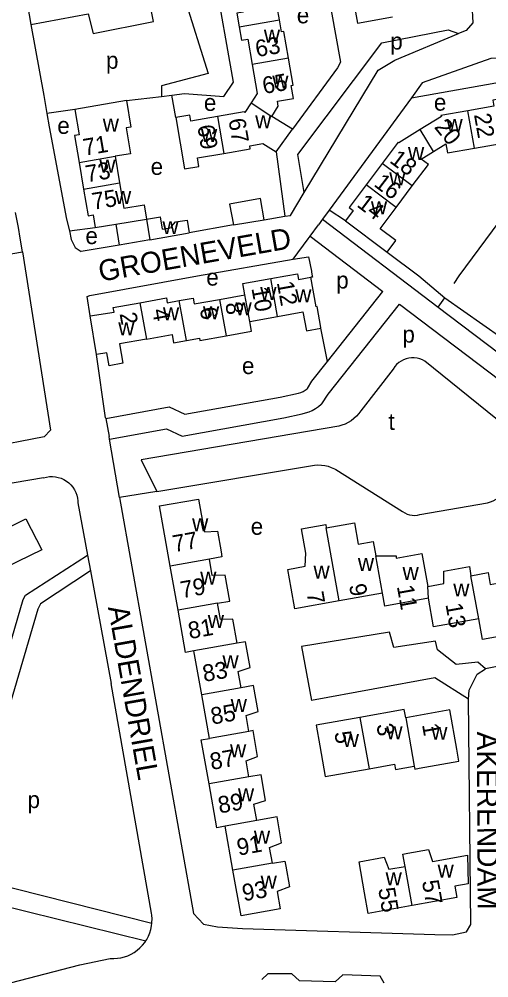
# Model space of a CAD drawing. Extents: x 157794 to 159375, y 380877 to 382306.
# Drawn here: x 158787.7 to 158899.5, y 381333.1 to 381561.1 of the extents above; entities that cross this region are included whole.
import ezdxf

# ---------------------------------------------------------------- set-up
doc = ezdxf.new("R2010")
doc.units = 0
for name, color, linetype in [('BLT_Basislijn', 7, 'Continuous'), ('BLT_Bebouwing', 7, 'Continuous'), ('BLT_Centroide', 7, 'Continuous'), ('BLT_Huisnummer', 7, 'Continuous'), ('BLT_Huisnummer_ tussenligend', 7, 'Continuous'), ('BLT_Onderverdeling_panden', 7, 'Continuous'), ('BLT_Straatnaam', 7, 'Continuous')]:
    doc.layers.add(name, color=color, linetype=linetype)

msp = doc.modelspace()

# ---------------------------------------------------------------- linework, layer by layer
at = {"layer": 'BLT_Basislijn'}
for p, q in [((158788.97, 381568.19), (158790.49, 381559.76)), ((158790.49, 381559.76), (158793.52, 381542.93)), ((158881.11, 381542.38), (158935.03, 381551.97)), ((158793.52, 381542.93), (158794.3, 381538.63)), ((158813.23, 381541.67), (158821.56, 381542.67)), ((158821.56, 381542.67), (158824.05, 381542.98)), ((158824.96, 381537.67), (158824.05, 381542.98)), ((158881.11, 381542.38), (158861.49, 381515.66)), ((158800.93, 381539.6), (158794.3, 381538.63)), ((158848.85, 381529.5), (158850.92, 381514.16)), ((158846.01, 381513.34), (158850.92, 381514.16)), ((158861.49, 381515.66), (158859.9, 381513.46)), ((158865.42, 381513.1), (158861.49, 381515.66)), ((158810.68, 381512.32), (158811.52, 381507.34)), ((158838.7, 381512.1), (158828.13, 381510.23)), ((158838.7, 381512.1), (158846.01, 381513.34)), ((158856.94, 381509.43), (158858.94, 381512.13)), ((158859.9, 381513.46), (158858.94, 381512.13)), ((158859.9, 381513.46), (158887.48, 381492.55)), ((158799.67, 381510.69), (158805.78, 381511.54)), ((158788.5, 381505.74), (158787.94, 381508.94)), ((158811.52, 381507.34), (158802.45, 381505.81)), ((158818.82, 381508.57), (158811.52, 381507.34)), ((158852.89, 381503.99), (158856.49, 381508.82)), ((158856.49, 381508.82), (158856.94, 381509.43)), ((158856.94, 381509.43), (158874.25, 381496.31)), ((158762.21, 381501.13), (158788.5, 381505.74)), ((158861.07, 381479.65), (158874.25, 381496.31)), ((158887.48, 381492.55), (158889.04, 381494.78)), ((158889.04, 381494.78), (158902.64, 381485.28)), ((158861.26, 381471.84), (158878.23, 381493.29)), ((158878.23, 381493.29), (158910.13, 381469.1)), ((158887.48, 381492.55), (158916.2, 381470.77)), ((158861.07, 381479.65), (158859.55, 381487.59)), ((158857.34, 381474.94), (158861.07, 381479.65)), ((158876.71, 381477.84), (158869.08, 381467.9)), ((158856.35, 381473.24), (158857.34, 381474.94)), ((158849.84, 381471.15), (158854.17, 381472.14)), ((158859.77, 381469.59), (158861.26, 381471.84)), ((158808.27, 381466.22), (158808.3, 381466.05)), ((158850.72, 381466.23), (158855.04, 381467.22)), ((158808.3, 381466.05), (158809.08, 381461.82)), ((158809.2, 381461.13), (158809.08, 381461.82)), ((158811.58, 381447.29), (158809.2, 381461.13)), ((158820.45, 381448.71), (158858.02, 381454.97)), ((158863.11, 381453.93), (158878.97, 381443.94)), ((158820.45, 381448.71), (158811.58, 381447.29)), ((158801.66, 381446.05), (158803.95, 381433.61)), ((158883.08, 381443.24), (158899.19, 381446.05)), ((158803.95, 381433.61), (158804.64, 381429.84)), ((158804.64, 381429.84), (158809.56, 381403.07)), ((158854.95, 381411.84), (158857.29, 381398.99)), ((158819.19, 381348.47), (158809.56, 381403.07)), ((158766.06, 381354.67), (158817.83, 381341.85))]:
    msp.add_line(p, q, dxfattribs=at)
for points in [[(158862.62, 381591.43), (158868.21, 381560.11), (158876.56, 381561.6)], [(158858.57, 381582.03), (158864.2, 381550.82), (158863.51, 381549.47), (158852.74, 381534.9)], [(158824.05, 381542.98), (158827.04, 381543.34), (158836.42, 381542.65), (158838.75, 381546.05), (158834.16, 381571.64), (158834.2, 381573.13), (158836.79, 381578.18)], [(158790.49, 381559.76), (158804.15, 381562.3), (158805.33, 381557.66), (158819.64, 381560.49), (158818.84, 381564.49), (158827.05, 381566.14), (158832.68, 381548.16), (158821.56, 381545.2), (158821.56, 381542.67)], [(158895.44, 381564.63), (158895.7, 381560.21), (158894.12, 381558.36), (158892.29, 381557.61)], [(158855.57, 381519.81), (158854.06, 381528.89), (158874.07, 381555.42), (158889.82, 381558.48), (158892.29, 381557.61)], [(158855.57, 381519.81), (158873.18, 381548.95), (158877.15, 381551.33), (158892.29, 381557.61)], [(158935.03, 381551.97), (158899.98, 381551.73), (158883.68, 381545.89), (158881.11, 381542.38)], [(158794.3, 381538.63), (158794.85, 381535.45), (158798.92, 381513.51), (158799.67, 381510.69)], [(158850.92, 381514.16), (158852.27, 381514.39), (158855.57, 381519.81)], [(158846.01, 381513.34), (158845.18, 381518.4), (158837.77, 381517.06), (158838.7, 381512.1)], [(158918.36, 381517.79), (158903.5, 381514.96), (158892.34, 381500), (158891.2, 381498.19)], [(158787.94, 381508.94), (158787.5, 381511.47), (158786.85, 381515.06)], [(158799.67, 381510.69), (158800.08, 381508.62), (158801.04, 381506.71), (158802.45, 381505.81)], [(158788.5, 381505.74), (158795.12, 381463.28), (158793.64, 381461.75), (158751.87, 381453.61), (158747.8, 381452.3)], [(158875.29, 381505.64), (158882.89, 381500), (158889.04, 381494.78)], [(158804.59, 381490.48), (158803.89, 381495.07), (158804.55, 381495.36), (158830.12, 381500), (158852.89, 381503.99)], [(158852.89, 381503.99), (158856.57, 381504.54), (158857.27, 381501.08)], [(158857.27, 381501.08), (158857.31, 381500.89), (158857.48, 381500), (158857.53, 381499.73), (158857.15, 381499.68)], [(158808.27, 381466.22), (158806.11, 381481.26)], [(158884.27, 381479.74), (158883.69, 381480.04), (158883.07, 381480.28), (158882.43, 381480.44), (158881.77, 381480.52), (158881.11, 381480.53), (158880.46, 381480.45), (158879.81, 381480.29), (158879.19, 381480.06), (158878.61, 381479.75), (158878.06, 381479.38), (158877.57, 381478.94), (158877.13, 381478.45), (158876.71, 381477.84)], [(158902.91, 381448.34), (158907.35, 381461.09), (158884.27, 381479.74)], [(158854.17, 381472.14), (158854.73, 381472.28), (158855.28, 381472.5), (158855.79, 381472.79), (158856.25, 381473.15), (158856.35, 381473.24)], [(158808.3, 381466.05), (158823.43, 381468.82), (158827.15, 381467.09), (158849.84, 381471.15)], [(158855.04, 381467.22), (158855.88, 381467.41), (158856.7, 381467.68), (158857.49, 381468.02), (158858.24, 381468.43), (158858.96, 381468.91), (158859.62, 381469.46), (158859.77, 381469.59)], [(158809.2, 381461.13), (158822.77, 381463.62), (158826.47, 381461.89), (158850.72, 381466.23)], [(158869.08, 381467.9), (158868.58, 381467.24), (158868.02, 381466.62), (158867.41, 381466.06), (158866.74, 381465.56), (158866.03, 381465.13), (158865.28, 381464.77), (158864.5, 381464.48), (158863.81, 381464.29)], [(158863.81, 381464.29), (158816.76, 381456.24), (158820.45, 381448.71)], [(158858.02, 381454.97), (158858.83, 381455.02), (158859.64, 381455), (158860.45, 381454.9), (158861.24, 381454.71), (158862.01, 381454.45), (158862.75, 381454.12), (158863.11, 381453.93)], [(158793.51, 381451.98), (158771.53, 381448.28), (158756.34, 381445.5), (158748.25, 381442.91), (158740.95, 381440.08), (158735.85, 381438.89)], [(158793.51, 381451.98), (158794.2, 381452.16), (158794.9, 381452.26), (158795.6, 381452.27), (158796.31, 381452.21), (158797, 381452.07), (158797.67, 381451.85), (158798.31, 381451.56), (158798.92, 381451.2), (158799.48, 381450.77), (158799.99, 381450.28), (158800.44, 381449.73), (158800.83, 381449.14), (158801.15, 381448.51), (158801.39, 381447.85), (158801.56, 381447.16), (158801.64, 381446.46), (158801.66, 381446.05)], [(158926.11, 381448.95), (158929.43, 381428.8), (158931.01, 381419.66), (158932.17, 381413.29), (158898.76, 381406.51)], [(158811.58, 381447.29), (158829.21, 381348.33), (158831.6, 381345.83), (158834.92, 381345.17), (158840.9, 381344.75), (158886.68, 381343.34), (158890.86, 381343.31), (158894.18, 381343.97), (158895.23, 381345.72), (158894.71, 381399.3)], [(158899.19, 381446.05), (158899.89, 381446.25), (158900.57, 381446.52), (158901.26, 381446.89)], [(158878.97, 381443.94), (158879.49, 381443.61), (158880.06, 381443.35), (158880.65, 381443.17), (158881.27, 381443.06), (158881.89, 381443.03), (158882.51, 381443.08), (158883.08, 381443.24)], [(158768.37, 381431.82), (158789.26, 381442.19), (158793.11, 381434.88), (158775.52, 381426.38)], [(158735.85, 381438.89), (158749.59, 381416.93), (158757.8, 381385.89), (158758.37, 381385.58), (158778.76, 381389.47), (158788.65, 381423.07), (158789.17, 381424.09), (158803.95, 381433.61)], [(158804.64, 381429.84), (158792.77, 381422.02), (158792.16, 381420.71), (158774.56, 381361.22), (158773.69, 381357.52), (158819.29, 381346.05)], [(158898.76, 381406.51), (158896.88, 381408.15), (158891.73, 381407.61), (158887.3, 381411.1), (158886.84, 381413.13), (158876.87, 381411.59), (158875.86, 381415.26), (158854.95, 381411.84)], [(158894.71, 381399.3), (158894.85, 381401.47), (158896.75, 381405.24), (158898.76, 381406.51)], [(158894.71, 381399.3), (158886.65, 381404.41), (158857.29, 381398.99)], [(158819.29, 381346.05), (158819.31, 381346.25), (158819.33, 381347.11), (158819.27, 381347.96), (158819.19, 381348.47)], [(158817.83, 381341.85), (158818.05, 381342.18), (158818.45, 381342.94), (158818.78, 381343.73), (158819.04, 381344.55), (158819.21, 381345.39), (158819.29, 381346.05)], [(158809.37, 381337.68), (158810.23, 381337.65), (158811.09, 381337.7), (158811.93, 381337.83), (158812.77, 381338.04), (158813.58, 381338.32), (158814.36, 381338.68), (158815.1, 381339.11), (158815.8, 381339.61), (158816.45, 381340.17), (158817.05, 381340.79), (158817.58, 381341.46), (158817.83, 381341.85)], [(158720.17, 381314.87), (158802.15, 381336.11), (158809.37, 381337.68)], [(158874.6, 381331.75), (158873.61, 381333.48), (158864.72, 381333.73), (158862.92, 381332.07), (158854.41, 381332.33), (158852.62, 381333.97), (158846.93, 381333.97), (158845.5, 381332.66)]]:
    msp.add_lwpolyline(points, dxfattribs=at)
at = {"layer": 'BLT_Bebouwing'}
for p, q in [((158813.23, 381541.67), (158800.93, 381539.6)), ((158810.55, 381528.45), (158811.61, 381522.1)), ((158801.94, 381527), (158803.01, 381520.65)), ((158874.16, 381526.75), (158870.33, 381521.65)), ((158877.46, 381516.3), (158881.29, 381521.4)), ((158817.41, 381516.93), (158817.99, 381513.49)), ((158817.99, 381513.49), (158821.31, 381514.07)), ((158821.8, 381511.12), (158821.31, 381514.07)), ((158805.78, 381511.54), (158810.68, 381512.32)), ((158810.68, 381512.32), (158817.99, 381513.49)), ((158817.99, 381513.49), (158818.82, 381508.57)), ((158865.42, 381513.1), (158875.29, 381505.64)), ((158818.82, 381508.57), (158828.13, 381510.23)), ((158835.4, 381494.4), (158841.44, 381495.5)), ((158806.11, 381481.26), (158804.59, 381490.48)), ((158842.59, 381489.16), (158849.22, 381490.36)), ((158825.52, 381420.48), (158823.65, 381430.95)), ((158874.17, 381424.55), (158863.91, 381422.72)), ((158863.91, 381422.72), (158853.31, 381420.82)), ((158831.15, 381400.37), (158829.29, 381410.79)), ((158833, 381389.99), (158831.15, 381400.37)), ((158868.81, 381394.97), (158858.37, 381393.11)), ((158838.58, 381358.62), (158836.71, 381369.1))]:
    msp.add_line(p, q, dxfattribs=at)
for points in [[(158839.95, 381568.88), (158841.01, 381562.71), (158839.53, 381562.45), (158840.08, 381559.24)], [(158849.67, 381560.9), (158849.15, 381563.91), (158849.65, 381564), (158848.55, 381570.37)], [(158851.83, 381551.75), (158850.73, 381558.13), (158850.17, 381558.03), (158849.67, 381560.9)], [(158840.08, 381559.24), (158840.64, 381556.04), (158842.14, 381556.3), (158843.19, 381550.26)], [(158847.88, 381537.94), (158849.37, 381540.33), (158849.16, 381541.54), (158853, 381542.21), (158852.47, 381545.3), (158852.93, 381545.38), (158851.83, 381551.75)], [(158843.19, 381550.26), (158844.37, 381543.4), (158842.91, 381541.13)], [(158813.23, 381541.67), (158814.29, 381535.4), (158813.15, 381535.21), (158814.2, 381529.02), (158810.55, 381528.45)], [(158903.66, 381542.38), (158900.5, 381541.82), (158900.75, 381540.38), (158894.5, 381539.27)], [(158800.93, 381539.6), (158801.95, 381533.54), (158800.88, 381533.36), (158801.94, 381527)], [(158842.91, 381541.13), (158841.45, 381538.85), (158841.23, 381539.01), (158834.92, 381537.92)], [(158894.5, 381539.27), (158888.1, 381538.14), (158888.21, 381537.9), (158883.17, 381534.78)], [(158834.92, 381537.92), (158828.6, 381536.83), (158828.36, 381538.25), (158824.96, 381537.67)], [(158824.96, 381537.67), (158827.07, 381525.46), (158830.45, 381526.04), (158830.11, 381528.04), (158836.43, 381529.13)], [(158852.74, 381534.9), (158847.88, 381537.94)], [(158848.85, 381529.5), (158852.74, 381534.9)], [(158883.17, 381534.78), (158878.1, 381531.63), (158877.93, 381531.76), (158874.16, 381526.75)], [(158896.07, 381530.35), (158902.44, 381531.48), (158902.35, 381531.97), (158905.4, 381532.51)], [(158836.43, 381529.13), (158842.71, 381530.22), (158842.59, 381530.92), (158845.71, 381531.46), (158848.85, 381529.5)], [(158886.36, 381529.57), (158889.3, 381531.38), (158889.7, 381529.23), (158896.07, 381530.35)], [(158881.29, 381521.4), (158885.12, 381526.5), (158883.42, 381527.77), (158886.36, 381529.57)], [(158811.61, 381522.1), (158812.62, 381516.12), (158817.41, 381516.93)], [(158870.33, 381521.65), (158866.29, 381516.27), (158867.25, 381515.55), (158865.42, 381513.1)], [(158803.01, 381520.65), (158804.08, 381514.3), (158805.28, 381514.5), (158805.78, 381511.54)], [(158875.29, 381505.64), (158877.36, 381508.4), (158873.63, 381511.2), (158877.46, 381516.3)], [(158821.8, 381511.12), (158824.05, 381511.48), (158823.99, 381511.73), (158824.93, 381512.85), (158827.69, 381513.23), (158828.13, 381510.23)], [(158847.59, 381499.35), (158851.17, 381500), (158853.99, 381500.51)], [(158853.99, 381500.51), (158854.07, 381500), (158854.23, 381499.15), (158857.15, 381499.68)], [(158841.44, 381495.5), (158840.96, 381498.15), (158847.59, 381499.35)], [(158859.55, 381487.59), (158859.52, 381487.76), (158858.63, 381492.68), (158858.43, 381492.64), (158857.15, 381499.68)], [(158804.59, 381490.48), (158810.3, 381491.37), (158810.1, 381492.48), (158816.41, 381493.62)], [(158816.41, 381493.62), (158822.73, 381494.77), (158822.94, 381493.61), (158825.81, 381494.12)], [(158825.81, 381494.12), (158829.11, 381494.72), (158829.37, 381493.31), (158835.4, 381494.4)], [(158849.22, 381490.36), (158855.26, 381491.45), (158856.07, 381486.96), (158859.55, 381487.59)], [(158836.97, 381485.74), (158843.01, 381486.83), (158842.59, 381489.16)], [(158817.98, 381484.98), (158811.57, 381483.81), (158812.4, 381479.24), (158809.08, 381478.63), (158808.58, 381481.66), (158806.11, 381481.26)], [(158817.98, 381484.98), (158824.09, 381486.08), (158824.46, 381484.05), (158827.54, 381484.61)], [(158827.54, 381484.61), (158830.62, 381485.17), (158830.72, 381484.61), (158836.97, 381485.74)], [(158823.65, 381430.95), (158821.1, 381445.27), (158830.4, 381446.93), (158831.05, 381443.29), (158831.79, 381439.13), (158834.89, 381439.26), (158835.77, 381434.34), (158835.98, 381433.15), (158832.99, 381432.62)], [(158860.82, 381440.05), (158867.56, 381441.26), (158868.43, 381436.22), (158871.98, 381436.86), (158872.6, 381433.38)], [(158853.31, 381420.82), (158852.43, 381425.75), (158851.64, 381430.19), (158855.81, 381430.93), (158855.91, 381434.03), (158854.88, 381439.84), (158860.67, 381440.87), (158860.82, 381440.05)], [(158834.91, 381422.15), (158837.83, 381422.67), (158836.73, 381428.85), (158833.68, 381428.76), (158832.99, 381432.62)], [(158872.6, 381433.38), (158877.48, 381433.41), (158877.47, 381432.87), (158883.56, 381433.95), (158884.96, 381426.12)], [(158884.96, 381426.12), (158888.8, 381426.81), (158888.83, 381429.78), (158894.88, 381430.86), (158895.26, 381428.69)], [(158895.26, 381428.69), (158899.35, 381429.42), (158899.84, 381426.62), (158901.56, 381426.93), (158902.67, 381423.97), (158906.52, 381424.66)], [(158885.16, 381423.34), (158874.72, 381421.47), (158874.17, 381424.55)], [(158897.14, 381418.44), (158886.37, 381416.52), (158885.16, 381423.34)], [(158839.59, 381412.62), (158838.56, 381418.39), (158835.6, 381418.27), (158834.91, 381422.15)], [(158829.29, 381410.79), (158827.31, 381410.43), (158825.52, 381420.48)], [(158908.18, 381415.33), (158898.02, 381413.52), (158897.14, 381418.44)], [(158840.51, 381402.04), (158839.82, 381405.9), (158842.67, 381406.85), (158841.58, 381412.98), (158839.59, 381412.62)], [(158842.41, 381391.67), (158841.73, 381395.47), (158844.56, 381396.39), (158843.46, 381402.57), (158840.51, 381402.04)], [(158879.74, 381394.89), (158879.39, 381396.86), (158868.81, 381394.97)], [(158881.77, 381383.42), (158881.9, 381382.69), (158882.97, 381382.88), (158892.4, 381384.56), (158891.89, 381387.42), (158890.23, 381396.76), (158879.74, 381394.89)], [(158842.39, 381380.85), (158841.71, 381384.65), (158844.47, 381385.66), (158843.37, 381391.84), (158842.41, 381391.67)], [(158858.37, 381393.11), (158859.24, 381388.19), (158860.54, 381380.92), (158871.06, 381382.76)], [(158832.89, 381379.16), (158831.02, 381389.64), (158833, 381389.99)], [(158871.06, 381382.76), (158877.07, 381383.83), (158877.28, 381382.63), (158881.77, 381383.42)], [(158844.24, 381370.44), (158843.55, 381374.32), (158846.37, 381375.2), (158845.27, 381381.37), (158842.39, 381380.85)], [(158836.71, 381369.1), (158834.74, 381368.75), (158832.89, 381379.16)], [(158847.99, 381360.3), (158847.32, 381364.07), (158850.18, 381365.14), (158849.08, 381371.31), (158844.24, 381370.44)], [(158879.6, 381359.57), (158879.08, 381362.49), (158880.27, 381362.7), (158885.19, 381363.58), (158886.1, 381360.73), (158894.47, 381362.22), (158894.57, 381355.4), (158891.44, 381354.84), (158891.92, 381352.15), (158881.27, 381350.25)], [(158881.27, 381350.25), (158870.8, 381348.38), (158869.92, 381353.3), (158868.61, 381360.66), (158874.63, 381361.73), (158875.74, 381358.89), (158879.6, 381359.57)], [(158847.99, 381360.3), (158850.94, 381360.83), (158851.15, 381359.61), (158852.03, 381354.69), (158849.13, 381353.57), (158849.87, 381349.43), (158840.52, 381347.77), (158838.58, 381358.62)]]:
    msp.add_lwpolyline(points, dxfattribs=at)
at = {"layer": 'BLT_Onderverdeling_panden'}
for p, q in [((158840.08, 381559.24), (158849.67, 381560.9)), ((158851.83, 381551.75), (158843.19, 381550.26)), ((158842.91, 381541.13), (158847.88, 381537.94)), ((158896.07, 381530.35), (158894.5, 381539.27)), ((158834.92, 381537.92), (158836.43, 381529.13)), ((158886.36, 381529.57), (158883.17, 381534.78)), ((158801.94, 381527), (158810.55, 381528.45)), ((158881.29, 381521.4), (158874.16, 381526.75)), ((158803.01, 381520.65), (158811.61, 381522.1)), ((158877.46, 381516.3), (158870.33, 381521.65)), ((158849.22, 381490.36), (158847.59, 381499.35)), ((158816.41, 381493.62), (158817.98, 381484.98)), ((158827.54, 381484.61), (158825.81, 381494.12)), ((158835.4, 381494.4), (158836.97, 381485.74)), ((158842.59, 381489.16), (158841.44, 381495.5)), ((158863.91, 381422.72), (158860.82, 381440.05)), ((158832.99, 381432.62), (158823.65, 381430.95)), ((158874.17, 381424.55), (158872.6, 381433.38)), ((158897.14, 381418.44), (158895.26, 381428.69)), ((158885.16, 381423.34), (158884.96, 381426.12)), ((158834.91, 381422.15), (158825.52, 381420.48)), ((158839.59, 381412.62), (158829.29, 381410.79)), ((158840.51, 381402.04), (158831.15, 381400.37)), ((158868.81, 381394.97), (158871.06, 381382.76)), ((158879.74, 381394.89), (158881.77, 381383.42)), ((158842.41, 381391.67), (158833, 381389.99)), ((158842.39, 381380.85), (158832.89, 381379.16)), ((158844.24, 381370.44), (158836.71, 381369.1)), ((158847.99, 381360.3), (158838.58, 381358.62)), ((158881.27, 381350.25), (158879.6, 381359.57))]:
    msp.add_line(p, q, dxfattribs=at)

# ---------------------------------------------------------------- texts
at = {"layer": 'BLT_Centroide'}
for s, p in [('e', (158853.79, 381560.06)), ('w', (158845.95, 381555.5)), ('p', (158876.04, 381553.83)), ('p', (158808.36, 381549.26)), ('w', (158847.95, 381544.58)), ('e', (158831.67, 381539.23)), ('e', (158886.44, 381539.29)), ('e', (158796.77, 381533.77)), ('w', (158807.58, 381534.33)), ('w', (158843.88, 381535.12)), ('w', (158889.44, 381534.25)), ('w', (158830.97, 381531.84)), ('w', (158880.27, 381527.56)), ('w', (158806.78, 381524.56)), ('e', (158818.99, 381524.01)), ('w', (158875.81, 381521.53)), ('w', (158810.5, 381517.09)), ('w', (158871.44, 381514.67)), ('w', (158821.79, 381509.93)), ('e', (158803.46, 381507.56)), ('e', (158832.24, 381497.68)), ('p', (158863.17, 381496.99)), ('w', (158845.09, 381494.25)), ('w', (158853.42, 381493.72)), ('w', (158839.2, 381490.62)), ('w', (158821.92, 381489.41)), ('w', (158831.45, 381489.66)), ('w', (158811.28, 381485.86)), ('p', (158878.94, 381484.12)), ('e', (158840.74, 381476.64)), ('t', (158875.62, 381463.35)), ('w', (158828.86, 381439.27)), ('e', (158842.82, 381438.42)), ('w', (158868.33, 381429.84)), ('w', (158857.77, 381428)), ('w', (158878.97, 381427.67)), ('w', (158830.79, 381426.56)), ('w', (158891.05, 381423.75)), ('w', (158832.6, 381416.28)), ('w', (158836.09, 381406.69)), ('w', (158838.05, 381396.28)), ('w', (158864.72, 381387.95)), ('w', (158875.11, 381389.78)), ('w', (158885.81, 381389.67)), ('w', (158837.89, 381385.5)), ('w', (158839.77, 381375.06)), ('p', (158789.67, 381373.42)), ('w', (158843.58, 381364.97)), ('w', (158887.31, 381356.91)), ('w', (158845.18, 381354.28)), ('w', (158874.94, 381355.05))]:
    msp.add_text(s, height=4, dxfattribs=at).set_placement(p)
at = {"layer": 'BLT_Huisnummer'}
for s, rotation, p in [('63', 9.8059, (158844.27, 381552.01)), ('22', 280.001, (158895.97, 381538.35)), ('69', 279.8068, (158830.09, 381535.64)), ('71', 9.5574, (158803.24, 381528.55)), ('18', 323.1108, (158875.67, 381527.13)), ('75', 9.1049, (158805.31, 381515.71)), ('14', 322.7282, (158867.88, 381516.64)), ('12', 280.2785, (158849.03, 381498.43)), ('2', 280.2774, (158811.58, 381491.02)), ('6', 280.2746, (158830.65, 381492.26)), ('77', 10.1136, (158824.59, 381434.27)), ('11', 280.1115, (158877.61, 381426.16)), ('7', 280.1122, (158856.12, 381424.6)), ('81', 10.1136, (158828.29, 381413.61)), ('85', 10.1136, (158833.65, 381393.27)), ('1', 280.1187, (158883.59, 381393.28)), ('5', 280.1212, (158862.71, 381391.4)), ('89', 10.1136, (158835.4, 381372.12)), ('93', 10.1136, (158841.14, 381351.25)), ('55', 280.1122, (158873.15, 381354.22)), ('57', 280.1215, (158883.58, 381356))]:
    msp.add_text(s, height=4, rotation=rotation, dxfattribs=at).set_placement(p)
at = {"layer": 'BLT_Huisnummer_ tussenligend'}
for s, rotation, p in [('65', 9.8059, (158845.96, 381543.24)), ('67', 279.8068, (158837.5, 381537.17)), ('20', 309.1108, (158886.37, 381535.34)), ('73', 9.5574, (158803.81, 381522.24)), ('16', 322.7282, (158871.93, 381521.52)), ('10', 280.2746, (158842.98, 381497.05)), ('8', 280.2746, (158836.72, 381493.43)), ('4', 280.2774, (158819.32, 381491.88)), ('79', 10.1136, (158826.45, 381423.31)), ('9', 280.1122, (158866.22, 381426.45)), ('13', 280.1115, (158889.18, 381421.88)), ('83', 10.1136, (158831.72, 381403.42)), ('3', 280.1187, (158872.73, 381393.22)), ('87', 10.1136, (158833.47, 381382.48)), ('91', 10.1136, (158839.89, 381362.09))]:
    msp.add_text(s, height=4, rotation=rotation, dxfattribs=at).set_placement(p)
at = {"layer": 'BLT_Straatnaam'}
for s, rotation, p in [('GROENEVELD', 9.9411, (158807.02, 381498.6)), ('ALDENDRIEL', 279.9849, (158808.8, 381421.18)), ('AKERENDAM', 270.2016, (158896.69, 381391.62))]:
    msp.add_text(s, height=5, rotation=rotation, dxfattribs=at).set_placement(p)

doc.saveas('drawing.dxf')
